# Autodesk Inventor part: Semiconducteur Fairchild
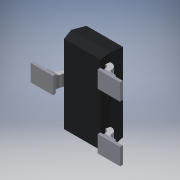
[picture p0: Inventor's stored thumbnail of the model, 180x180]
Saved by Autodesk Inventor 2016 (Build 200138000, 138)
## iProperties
Created: 2018-03
Part Number: Semiconducteur Fairchild
Material: Générique
Document SubType Name: Modeling
Designer: Bruno
Density: 1 g/cm^3
Appearance: Par défaut
Author: Bruno
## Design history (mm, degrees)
feature "Composite1"
body "Srf1"
